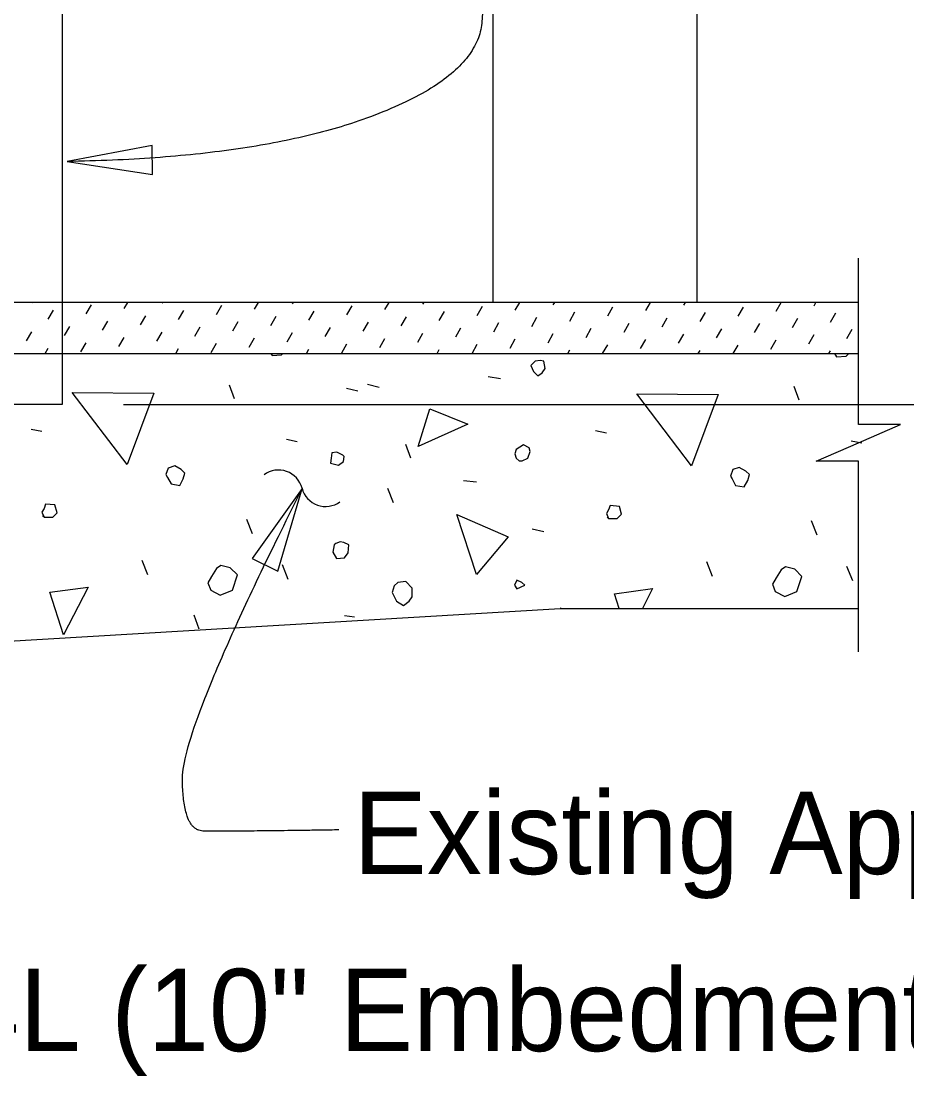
# Model space of a CAD drawing. Extents: x 21526.6 to 21595.9, y 56114.9 to 56157.2.
# Drawn here: x 21539.631 to 21541.802, y 56132.565 to 56135.149 of the extents above; entities that cross this region are included whole.
import ezdxf

# ---------------------------------------------------------------- set-up
doc = ezdxf.new("R2010")
doc.units = 0
for name, color, linetype in [('AdhocPoint_dp', 7, 'Continuous'), ('Border', 7, 'Continuous'), ('Patterning', 7, 'Continuous'), ('PlotBorder_dp', 7, 'Continuous'), ('SubStrConc', 7, 'Continuous'), ('SubStrConc_h', 7, 'Continuous')]:
    doc.layers.add(name, color=color, linetype=linetype)

msp = doc.modelspace()

# ---------------------------------------------------------------- linework, layer by layer
at = {"layer": 'AdhocPoint_dp'}
for p, q in [((21535.7321, 56134.4601), (21541.6829, 56134.4601)), ((21537.6185, 56134.335), (21541.6829, 56134.335)), ((21536.7321, 56133.4601), (21540.9521, 56133.71)), ((21540.9521, 56133.7101), (21541.6829, 56133.7101))]:
    msp.add_line(p, q, dxfattribs=at)
at = {"layer": 'Patterning'}
for p, q in [((21540.7867, 56137.2725), (21540.7867, 56134.4601)), ((21541.2867, 56137.2725), (21541.2867, 56134.4601)), ((21539.6577, 56134.4588), (21539.6584, 56134.46)), ((21539.6978, 56134.4188), (21539.7108, 56134.4412)), ((21539.7909, 56134.4317), (21539.8039, 56134.4541)), ((21539.884, 56134.4447), (21539.8929, 56134.46)), ((21539.9771, 56134.4577), (21539.9785, 56134.46)), ((21540.0172, 56134.4176), (21540.0301, 56134.44)), ((21540.1103, 56134.4306), (21540.1232, 56134.4529)), ((21540.2034, 56134.4435), (21540.2129, 56134.46)), ((21540.2965, 56134.4565), (21540.2985, 56134.46)), ((21540.4297, 56134.4294), (21540.4426, 56134.4518)), ((21540.5228, 56134.4423), (21540.533, 56134.46)), ((21540.6159, 56134.4553), (21540.6186, 56134.46)), ((21540.749, 56134.4282), (21540.762, 56134.4506)), ((21540.8421, 56134.4412), (21540.8531, 56134.46)), ((21540.9352, 56134.4541), (21540.9387, 56134.46)), ((21541.0684, 56134.427), (21541.0814, 56134.4494)), ((21541.1615, 56134.44), (21541.1731, 56134.46)), ((21541.2546, 56134.4529), (21541.2587, 56134.46)), ((21541.3878, 56134.4258), (21541.4008, 56134.4482)), ((21541.4809, 56134.4388), (21541.4932, 56134.46)), ((21541.574, 56134.4518), (21541.5788, 56134.46)), ((21539.831, 56134.3917), (21539.8439, 56134.4141)), ((21539.9241, 56134.4046), (21539.937, 56134.427)), ((21540.2435, 56134.4034), (21540.2564, 56134.4258)), ((21540.3366, 56134.4164), (21540.3495, 56134.4388)), ((21540.5628, 56134.4023), (21540.5758, 56134.4247)), ((21540.6559, 56134.4152), (21540.6689, 56134.4376)), ((21540.8822, 56134.4011), (21540.8952, 56134.4235)), ((21540.9753, 56134.4141), (21540.9883, 56134.4364)), ((21541.2016, 56134.3999), (21541.2145, 56134.4223)), ((21541.2947, 56134.4129), (21541.3077, 56134.4353)), ((21541.521, 56134.3987), (21541.5339, 56134.4211)), ((21541.6141, 56134.4117), (21541.627, 56134.4341)), ((21539.6448, 56134.3657), (21539.6577, 56134.3881)), ((21539.7379, 56134.3787), (21539.7508, 56134.4011)), ((21540.0572, 56134.3775), (21540.0702, 56134.3999)), ((21540.1504, 56134.3905), (21540.1633, 56134.4129)), ((21540.3766, 56134.3763), (21540.3896, 56134.3987)), ((21540.4697, 56134.3893), (21540.4827, 56134.4117)), ((21540.696, 56134.3752), (21540.709, 56134.3976)), ((21540.7891, 56134.3881), (21540.8021, 56134.4105)), ((21541.0154, 56134.374), (21541.0283, 56134.3964)), ((21541.1085, 56134.387), (21541.1214, 56134.4093)), ((21541.3348, 56134.3728), (21541.3477, 56134.3952)), ((21541.4279, 56134.3858), (21541.4408, 56134.4082)), ((21541.6541, 56134.3716), (21541.6671, 56134.394)), ((21539.871, 56134.3516), (21539.884, 56134.374)), ((21539.9641, 56134.3646), (21539.9771, 56134.387)), ((21540.1904, 56134.3504), (21540.2034, 56134.3728)), ((21540.2835, 56134.3634), (21540.2965, 56134.3858)), ((21540.5098, 56134.3492), (21540.5228, 56134.3716)), ((21540.6029, 56134.3622), (21540.6159, 56134.3846)), ((21540.8292, 56134.3481), (21540.8421, 56134.3705)), ((21540.9223, 56134.361), (21540.9352, 56134.3834)), ((21541.1486, 56134.3469), (21541.1615, 56134.3693)), ((21541.2417, 56134.3598), (21541.2546, 56134.3822)), ((21541.4679, 56134.3457), (21541.4809, 56134.3681)), ((21541.561, 56134.3587), (21541.574, 56134.3811)), ((21539.6902, 56134.335), (21539.6978, 56134.3481)), ((21539.7779, 56134.3386), (21539.7909, 56134.361)), ((21540.0103, 56134.335), (21540.0172, 56134.3469)), ((21540.0973, 56134.3375), (21540.1103, 56134.3598)), ((21540.3304, 56134.335), (21540.3366, 56134.3457)), ((21540.4167, 56134.3363), (21540.4297, 56134.3587)), ((21540.6504, 56134.335), (21540.6559, 56134.3445)), ((21540.7361, 56134.3351), (21540.749, 56134.3575)), ((21540.9705, 56134.335), (21540.9753, 56134.3433)), ((21541.0561, 56134.335), (21541.0684, 56134.3563)), ((21541.2905, 56134.335), (21541.2947, 56134.3422)), ((21541.3761, 56134.335), (21541.3878, 56134.3551)), ((21541.6106, 56134.335), (21541.6141, 56134.341)), ((21540.4799, 56134.2595), (21540.5082, 56134.2524)), ((21540.7756, 56134.2785), (21540.8056, 56134.2732)), ((21540.1542, 56134.2237), (21540.1418, 56134.2573)), ((21540.4282, 56134.2502), (21540.4565, 56134.2431)), ((21541.5375, 56134.2202), (21541.5251, 56134.2537)), ((21539.6557, 56134.1494), (21539.6822, 56134.1441)), ((21541.0389, 56134.1459), (21541.0655, 56134.1406)), ((21540.2815, 56134.1247), (21540.308, 56134.1194)), ((21540.586, 56134.0783), (21540.5736, 56134.1119)), ((21541.6647, 56134.1212), (21541.6913, 56134.1159)), ((21540.5435, 56133.9687), (21540.5294, 56134.004)), ((21540.7154, 56134.0239), (21540.7473, 56134.0204)), ((21540.1984, 56133.8931), (21540.1842, 56133.9285)), ((21541.5817, 56133.8896), (21541.5675, 56133.9249)), ((21540.8834, 56133.9055), (21540.9117, 56133.8984)), ((21539.9421, 56133.7924), (21539.9279, 56133.8277)), ((21541.3253, 56133.7888), (21541.3112, 56133.8242)), ((21540.2854, 56133.7813), (21540.2713, 56133.8167)), ((21541.6687, 56133.7778), (21541.6546, 56133.8131)), ((21540.0676, 56133.6598), (21540.0552, 56133.6934)), ((21540.4233, 56133.6929), (21540.4481, 56133.6894))]:
    msp.add_line(p, q, dxfattribs=at)
for points in [[(21540.2429, 56134.335), (21540.2461, 56134.3298), (21540.2691, 56134.3315), (21540.2725, 56134.335)], [(21540.8869, 56134.2909), (21540.8975, 56134.2803), (21540.9081, 56134.2873), (21540.9152, 56134.2979), (21540.9117, 56134.3156), (21540.9028, 56134.3174), (21540.8905, 56134.3156), (21540.8799, 56134.305), (21540.8869, 56134.2909)], [(21541.624, 56134.335), (21541.6294, 56134.3262), (21541.6524, 56134.328), (21541.6594, 56134.335)], [(21539.8908, 56134.0628), (21539.7564, 56134.2396), (21539.9562, 56134.2378), (21539.8908, 56134.0628)], [(21541.2741, 56134.0593), (21541.1397, 56134.2361), (21541.3395, 56134.2343), (21541.2741, 56134.0593)], [(21540.6041, 56134.107), (21540.6324, 56134.1989), (21540.7261, 56134.1618), (21540.6041, 56134.107)], [(21540.8516, 56134.0717), (21540.8586, 56134.0717), (21540.8728, 56134.0787), (21540.8781, 56134.0946), (21540.8763, 56134.1035), (21540.8622, 56134.1106), (21540.8445, 56134.0999), (21540.841, 56134.0893), (21540.8445, 56134.0787), (21540.8516, 56134.0717)], [(21540.3893, 56134.0664), (21540.4087, 56134.0611), (21540.4211, 56134.0699), (21540.4229, 56134.0823), (21540.4193, 56134.0858), (21540.4052, 56134.0929), (21540.3928, 56134.0911), (21540.3911, 56134.0787), (21540.3893, 56134.0664)], [(21539.9898, 56134.031), (21539.9986, 56134.0151), (21540.0198, 56134.0116), (21540.0287, 56134.0275), (21540.0322, 56134.0416), (21540.0234, 56134.0505), (21540.0075, 56134.0593), (21539.9915, 56134.054), (21539.9862, 56134.0381), (21539.9898, 56134.031)], [(21541.3731, 56134.0275), (21541.3819, 56134.0116), (21541.4031, 56134.008), (21541.4119, 56134.0239), (21541.4155, 56134.0381), (21541.4066, 56134.0469), (21541.3907, 56134.0558), (21541.3748, 56134.0505), (21541.3695, 56134.0345), (21541.3731, 56134.0275)], [(21539.6875, 56133.9338), (21539.7087, 56133.9338), (21539.7193, 56133.9444), (21539.714, 56133.9638), (21539.691, 56133.9656), (21539.6875, 56133.955), (21539.6822, 56133.9462), (21539.6875, 56133.9338), (21539.684, 56133.9373)], [(21541.0708, 56133.9302), (21541.092, 56133.9302), (21541.1026, 56133.9409), (21541.0973, 56133.9603), (21541.0743, 56133.9621), (21541.0708, 56133.9515), (21541.0655, 56133.9426), (21541.0708, 56133.9302), (21541.0672, 56133.9338)], [(21540.7468, 56133.7937), (21540.6991, 56133.9404), (21540.8246, 56133.8856), (21540.7468, 56133.7937)], [(21540.395, 56133.8485), (21540.4039, 56133.8326), (21540.4233, 56133.8343), (21540.4322, 56133.8467), (21540.4339, 56133.8662), (21540.4216, 56133.8715), (21540.4127, 56133.8732), (21540.4021, 56133.8697), (21540.3986, 56133.8662), (21540.395, 56133.8485)], [(21540.0958, 56133.7552), (21540.1188, 56133.7429), (21540.1489, 56133.7552), (21540.1613, 56133.7924), (21540.1436, 56133.81), (21540.1206, 56133.8153), (21540.11, 56133.8083), (21540.0976, 56133.7888), (21540.0888, 56133.7729), (21540.0958, 56133.7552)], [(21541.4791, 56133.7517), (21541.5021, 56133.7393), (21541.5322, 56133.7517), (21541.5445, 56133.7888), (21541.5269, 56133.8065), (21541.5039, 56133.8118), (21541.4933, 56133.8047), (21541.4809, 56133.7853), (21541.4721, 56133.7694), (21541.4791, 56133.7517)], [(21540.54, 56133.7495), (21540.5506, 56133.7283), (21540.5683, 56133.7177), (21540.5824, 56133.7283), (21540.5895, 56133.7389), (21540.5895, 56133.7601), (21540.5736, 56133.776), (21540.5541, 56133.7742), (21540.5453, 56133.7654), (21540.54, 56133.7495)], [(21540.8458, 56133.7583), (21540.8653, 56133.7672), (21540.8582, 56133.7742), (21540.8458, 56133.7795), (21540.8405, 56133.7672), (21540.8458, 56133.7583)], [(21539.7352, 56133.6456), (21539.7016, 56133.7499), (21539.7953, 56133.7623), (21539.7352, 56133.6456)], [(21541.0966, 56133.71), (21541.0849, 56133.7464), (21541.1786, 56133.7588), (21541.1535, 56133.71)], [(21540.9547, 56133.71), (21540.9537, 56133.7106), (21540.9522, 56133.71)]]:
    msp.add_lwpolyline(points, dxfattribs=at)
at = {"layer": 'PlotBorder_dp'}
msp.add_line((21539.8821, 56134.2101), (21543.3608, 56134.2101), dxfattribs=at)
for points in [[(21539.7444, 56134.8051), (21539.9532, 56134.7733), (21539.9521, 56134.8439)], [(21540.3202, 56134.0044), (21540.1971, 56133.8327), (21540.2605, 56133.8018)]]:
    msp.add_lwpolyline(points, close=True, dxfattribs=at)
msp.add_lwpolyline([(21541.6829, 56133.6036), (21541.6829, 56134.0708), (21541.5795, 56134.0708), (21541.6829, 56134.1158), (21541.7862, 56134.1608), (21541.6829, 56134.1608), (21541.6829, 56134.5682)], dxfattribs=at)
for centre, start, end in [((21540.2618, 56133.9896), 14.5413, 126.2686), ((21540.3772, 56134.0195), 194.5413, 306.2686)]:
    msp.add_arc(centre, 0.0596, start, end, dxfattribs=at)
for points in [[(21542.0754, 56135.9047), (21541.4139, 56135.9116), (21541.1398, 56135.7744), (21540.9568, 56135.6032), (21540.7613, 56135.3058), (21540.7613, 56135.0162), (21540.2137, 56134.8128), (21539.7444, 56134.8049)], [(21540.4101, 56133.1678), (21540.1274, 56133.1634), (21540.0268, 56133.1666), (21540.0268, 56133.4222), (21540.3202, 56134.0043)]]:
    msp.add_open_spline(points, degree=2, dxfattribs=at)
at = {"layer": 'SubStrConc'}
msp.add_line((21539.7321, 56135.2101), (21539.7321, 56134.46), dxfattribs=at)
at = {"layer": 'SubStrConc_h'}
msp.add_lwpolyline([(21539.7321, 56134.46), (21539.7321, 56134.2101), (21537.6216, 56134.2101)], dxfattribs=at)

# ---------------------------------------------------------------- texts
at = {"layer": 'Border'}
for s, p in [('Existing Approach Slab', (21540.4455, 56133.0596)), ('Dowel Bars 4L (10" Embedment) (See Note 2)', (21538.0238, 56132.6259))]:
    msp.add_text(s, height=0.2016, dxfattribs=at).set_placement(p)

doc.saveas('drawing.dxf')
